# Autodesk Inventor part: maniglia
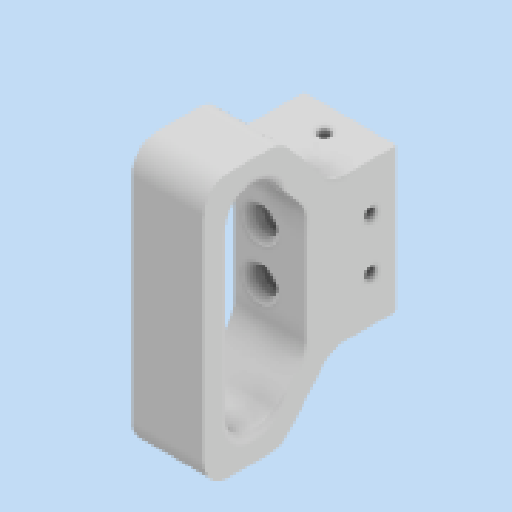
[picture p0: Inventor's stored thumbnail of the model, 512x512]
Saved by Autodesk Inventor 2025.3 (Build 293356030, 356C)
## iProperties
Created: 2025-11
Part Number: maniglia
Material: Generico
Document SubType Name: Modeling
Designer: Ryzen5700u
Density: 1 g/cm^3
Appearance: Default
Author: Ryzen5700u
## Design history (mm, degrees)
feature "Solido1"
node "Solido2"
